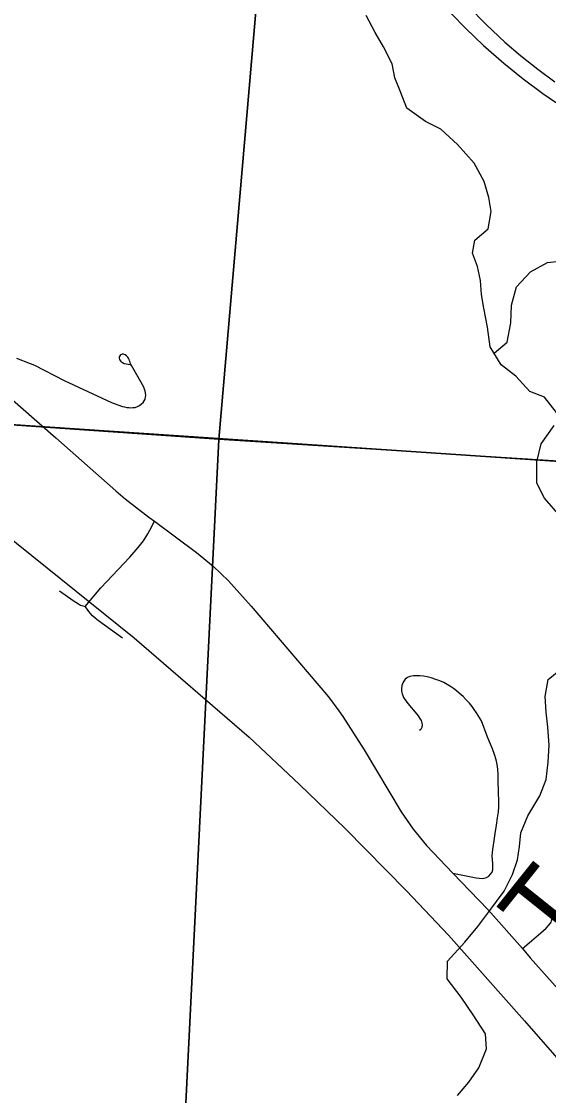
# Model space of a CAD drawing. Extents: x 39.8 to 73.8, y 13 to 35.
# Drawn here: x 47.078 to 47.463, y 27.389 to 28.175 of the extents above; entities that cross this region are included whole.
import ezdxf

# ---------------------------------------------------------------- set-up
doc = ezdxf.new("R2010")
doc.units = 0
for name, color, linetype in [('GM_X_Corporation', 7, 'Continuous'), ('GM_X_County_Road', 7, 'Continuous'), ('GM_X_Minor_River', 7, 'Continuous'), ('GM_X_Rail_Line', 7, 'Continuous'), ('GM_X_Township_Road', 7, 'Continuous'), ('GM_X_Township_Road_Text', 7, 'Continuous'), ('GM_X_US_Route', 7, 'Continuous')]:
    doc.layers.add(name, color=color, linetype=linetype)

msp = doc.modelspace()

# ---------------------------------------------------------------- linework, layer by layer
at = {"layer": 'GM_X_Corporation'}
msp.add_lwpolyline([(43.33042, 29.73647), (43.27257, 28.95026), (43.2721, 28.94382), (43.21308, 28.14161), (43.99916, 28.08829), (44.12704, 28.07962), (44.14223, 28.07859), (45.30639, 27.99962), (46.17667, 27.94059), (46.60108, 27.9118), (46.7316, 27.90295), (46.77749, 27.89983), (46.79052, 27.89895), (47.09502, 27.87829), (47.51487, 27.84982)], dxfattribs=at)
for points in [[(46.28582, 28.96471), (47.30013, 28.91155), (47.3019, 28.79184), (47.22222, 27.86899), (46.24519, 27.93679)], [(47.30013, 28.91155), (48.3118, 28.85726), (48.25863, 27.80295), (47.22222, 27.86899), (47.3019, 28.79184)], [(43.1433, 27.06498), (48.66298, 27.06498), (48.66298, 27.78088), (47.54138, 27.84843), (47.51487, 27.84982), (47.09502, 27.87829), (46.79052, 27.89895), (46.77749, 27.89983), (46.7316, 27.90295), (46.60108, 27.9118), (46.17667, 27.94059), (45.30639, 27.99962), (44.14223, 28.07859), (44.12704, 28.07962), (43.99916, 28.08829), (43.21308, 28.14161)], [(46.16091, 27.06498), (47.18234, 27.06498), (47.22222, 27.86899), (46.24519, 27.93679)], [(47.18234, 27.06498), (48.19551, 27.06498), (48.25863, 27.80295), (47.22222, 27.86899)]]:
    msp.add_lwpolyline(points, close=True, dxfattribs=at)
at = {"layer": 'GM_X_County_Road'}
for points in [[(46.80526, 28.19183), (46.8208, 28.16863), (46.82235, 28.16639), (46.83147, 28.15325), (46.8445, 28.13446), (46.88812, 28.07159), (46.89064, 28.06796), (46.89352, 28.06383), (46.90761, 28.04354), (46.91523, 28.03381), (46.91896, 28.02991), (46.92374, 28.0249), (46.95905, 27.99454), (46.96796, 27.98699), (47.01255, 27.94928), (47.0411, 27.92512), (47.06759, 27.90145), (47.0773, 27.89289), (47.10298, 27.87025)], [(47.10298, 27.87025), (47.147, 27.83145), (47.15384, 27.82542), (47.17103, 27.81218), (47.1752, 27.80909), (47.20605, 27.78631), (47.21807, 27.77637), (47.22928, 27.76552), (47.24597, 27.74701), (47.3024, 27.68069), (47.31004, 27.67051), (47.31297, 27.66632), (47.32849, 27.64199), (47.3556, 27.59665), (47.3644, 27.58394), (47.37418, 27.57199), (47.39341, 27.55177), (47.40585, 27.53884), (47.41929, 27.52487), (47.44419, 27.49656), (47.44991, 27.48983), (47.46015, 27.4784), (47.46823, 27.46917), (47.49049, 27.44379)]]:
    msp.add_lwpolyline(points, dxfattribs=at)
at = {"layer": 'GM_X_Minor_River'}
for points in [[(47.46918, 27.88868), (47.46038, 27.89997), (47.44975, 27.90404), (47.43944, 27.91531), (47.42877, 27.92355), (47.42071, 27.93674), (47.41869, 27.95112), (47.41592, 27.96512), (47.41432, 27.97496), (47.41347, 27.98518), (47.41149, 27.99539), (47.40762, 28.00521), (47.40943, 28.0147), (47.4192, 28.02313), (47.42136, 28.03565), (47.41976, 28.04587), (47.41625, 28.05759), (47.40894, 28.07116), (47.39672, 28.08469), (47.38451, 28.09595), (47.37349, 28.10153), (47.35978, 28.11126), (47.35513, 28.12334), (47.35088, 28.13354), (47.3489, 28.14375), (47.34274, 28.1562), (47.33659, 28.16675), (47.33005, 28.1792)], [(47.42362, 27.93198), (47.43316, 27.94026), (47.43569, 27.95431), (47.43633, 27.9672), (47.44, 27.9805), (47.45012, 27.99158), (47.46255, 27.99851), (47.47351, 27.99975)], [(47.47173, 27.81291), (47.46026, 27.82607), (47.45487, 27.83701), (47.45474, 27.85255), (47.45803, 27.86584), (47.46737, 27.87919)], [(47.39672, 27.38895), (47.40496, 27.39887), (47.41244, 27.40917), (47.41799, 27.42324), (47.41714, 27.43423), (47.40831, 27.44817), (47.3995, 27.46097), (47.38917, 27.47452), (47.38943, 27.4874), (47.40218, 27.50116), (47.41154, 27.51262), (47.41977, 27.5233), (47.43099, 27.53856), (47.43693, 27.55074), (47.44062, 27.56139), (47.44205, 27.57125), (47.4431, 27.58111), (47.44829, 27.59367), (47.45687, 27.60815), (47.46168, 27.62031), (47.46308, 27.63283), (47.46373, 27.64534), (47.46286, 27.6586), (47.46163, 27.66958), (47.46077, 27.68094), (47.46294, 27.69346), (47.47872, 27.70611)]]:
    msp.add_lwpolyline(points, dxfattribs=at)
at = {"layer": 'GM_X_Rail_Line'}
msp.add_lwpolyline([(46.69268, 28.45583), (46.79975, 28.13066), (46.81961, 28.06668), (46.82663, 28.04831), (46.83799, 28.02577), (46.84789, 28.00716), (46.86005, 27.98803), (46.87337, 27.96868), (46.89525, 27.94268), (46.91195, 27.92567), (46.92897, 27.91044), (46.95032, 27.8929), (47.01046, 27.84438), (47.16024, 27.72389), (47.24434, 27.65129), (47.28129, 27.6165), (47.31454, 27.58433), (47.35954, 27.53887), (47.39016, 27.50624), (47.44583, 27.44376), (47.49315, 27.38949)], dxfattribs=at)
at = {"layer": 'GM_X_Township_Road'}
for points in [[(47.07441, 27.92845), (47.08438, 27.92461), (47.08758, 27.9232), (47.10921, 27.91199), (47.14375, 27.89612), (47.14844, 27.89427), (47.15191, 27.89319), (47.15338, 27.8928), (47.15504, 27.89245), (47.15652, 27.89226), (47.15793, 27.89217), (47.15947, 27.89223), (47.16098, 27.8924), (47.16275, 27.89303), (47.16414, 27.89382), (47.16562, 27.89491), (47.16684, 27.89604), (47.16776, 27.89712), (47.16835, 27.8984), (47.16873, 27.89997), (47.1688, 27.90132), (47.16868, 27.9028), (47.1684, 27.90442), (47.16796, 27.90584), (47.16736, 27.90724), (47.16645, 27.90887), (47.16521, 27.91106), (47.15834, 27.92301), (47.15799, 27.92385), (47.1577, 27.92464), (47.15739, 27.9255), (47.15705, 27.92644), (47.1566, 27.92752), (47.15616, 27.92832), (47.15567, 27.92905), (47.15516, 27.92963), (47.15463, 27.93019), (47.15376, 27.93086), (47.15312, 27.9311), (47.15255, 27.93125), (47.15146, 27.93127), (47.15046, 27.93084), (47.14982, 27.93019), (47.14947, 27.92946), (47.14934, 27.92843), (47.14957, 27.92747), (47.15005, 27.92668), (47.15085, 27.92581), (47.15184, 27.92517), (47.15315, 27.92459), (47.15443, 27.92424), (47.156, 27.92402), (47.15746, 27.92387)], [(47.15181, 27.72364), (47.13425, 27.73638), (47.1319, 27.73823), (47.13, 27.73989), (47.12833, 27.74174), (47.12716, 27.74316), (47.12616, 27.74447), (47.12447, 27.74669), (47.13594, 27.76039), (47.15724, 27.78285), (47.16335, 27.78984), (47.1671, 27.79475), (47.17043, 27.79995), (47.17186, 27.80269), (47.1752, 27.80909)], [(47.10566, 27.75824), (47.11578, 27.75105), (47.11958, 27.74867), (47.12115, 27.74786), (47.12447, 27.74669)], [(47.39341, 27.55177), (47.41044, 27.54831), (47.41251, 27.54803), (47.41471, 27.54785), (47.41629, 27.54799), (47.41798, 27.54845), (47.41956, 27.5494), (47.42089, 27.55101), (47.422, 27.55246), (47.42251, 27.55415), (47.42262, 27.55623), (47.42258, 27.55856), (47.42233, 27.56163), (47.42214, 27.56449), (47.42225, 27.56675), (47.42266, 27.56909), (47.42316, 27.57223), (47.42422, 27.5808), (47.42522, 27.58691), (47.42613, 27.59214), (47.42674, 27.59646), (47.42704, 27.60012), (47.42703, 27.60325), (47.42673, 27.612), (47.42658, 27.61858), (47.42658, 27.62396), (47.42637, 27.62775), (47.4258, 27.63126), (47.42501, 27.63469), (47.42387, 27.63849), (47.42229, 27.64264), (47.42014, 27.6478), (47.41838, 27.65203), (47.41422, 27.66319), (47.41064, 27.66896), (47.40899, 27.6714), (47.40748, 27.67352), (47.40549, 27.67595), (47.40321, 27.67854), (47.40089, 27.68088), (47.39807, 27.6834), (47.39607, 27.68506), (47.39392, 27.68681), (47.39166, 27.68834), (47.38924, 27.6898), (47.38668, 27.69113), (47.38388, 27.69241), (47.38099, 27.69344), (47.37761, 27.69449), (47.37451, 27.69525), (47.37186, 27.69576), (47.36922, 27.69602), (47.36714, 27.69616), (47.36453, 27.69607), (47.362, 27.69552), (47.36015, 27.69474), (47.35859, 27.69351), (47.3571, 27.69145), (47.35616, 27.68897), (47.35578, 27.68622), (47.35587, 27.68501), (47.35601, 27.68388), (47.3563, 27.68282), (47.35675, 27.68161), (47.35739, 27.68023), (47.35824, 27.67881), (47.35923, 27.67745), (47.36052, 27.6758), (47.36699, 27.66796), (47.36791, 27.66684), (47.36885, 27.66558), (47.36959, 27.66438), (47.37015, 27.66333), (47.37051, 27.66245), (47.37068, 27.66181), (47.37078, 27.66119), (47.37083, 27.66061), (47.37085, 27.65998), (47.37081, 27.65936), (47.37073, 27.6588), (47.37058, 27.65823), (47.37042, 27.65776), (47.37022, 27.65732), (47.36998, 27.65691), (47.36893, 27.65601)], [(47.44419, 27.49656), (47.44907, 27.50084), (47.45771, 27.50809), (47.46152, 27.51153), (47.46331, 27.51345), (47.46487, 27.51523), (47.46529, 27.51596), (47.46561, 27.51689), (47.46565, 27.51763), (47.46552, 27.51855), (47.46529, 27.51937), (47.46472, 27.52044), (47.46412, 27.52141), (47.46309, 27.52275), (47.46212, 27.52379), (47.46091, 27.52489), (47.45953, 27.52628), (47.45871, 27.52735), (47.45792, 27.52859), (47.45732, 27.52966), (47.457, 27.53037), (47.45692, 27.53183)]]:
    msp.add_lwpolyline(points, dxfattribs=at)
at = {"layer": 'GM_X_US_Route'}
for points in [[(47.31598, 28.29189), (47.31873, 28.28657), (47.32836, 28.26921), (47.33916, 28.25109), (47.34918, 28.23542), (47.35869, 28.22164), (47.36989, 28.20679), (47.3817, 28.19242), (47.39244, 28.1804), (47.40276, 28.16969), (47.41576, 28.15728), (47.43068, 28.14419), (47.44466, 28.1329), (47.45908, 28.12217), (47.4739, 28.11199)], [(47.32998, 28.29177), (47.34067, 28.27203), (47.35077, 28.25487), (47.36067, 28.23977), (47.37054, 28.22616), (47.38051, 28.2134), (47.39212, 28.19957), (47.40469, 28.18576), (47.41781, 28.17247), (47.43146, 28.15972), (47.44276, 28.14994), (47.45542, 28.13986), (47.46797, 28.13065)]]:
    msp.add_lwpolyline(points, dxfattribs=at)

# ---------------------------------------------------------------- texts
at = {"layer": 'GM_X_Township_Road_Text'}
msp.add_text('T', height=0.05682, rotation=51.34956, dxfattribs=at).set_placement((47.46854, 27.49041))

doc.saveas('drawing.dxf')
